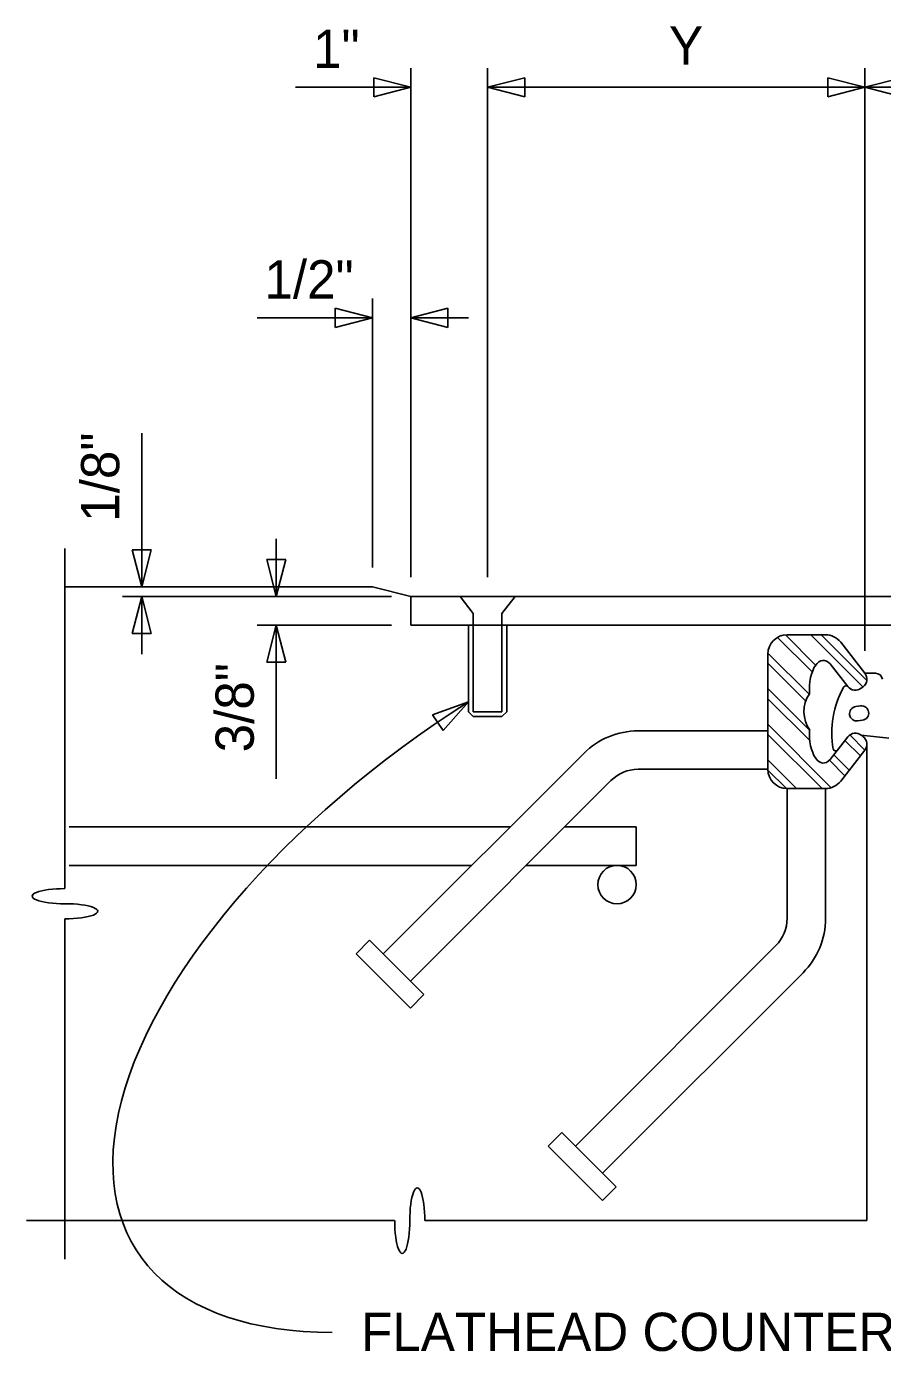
# Model space of a CAD drawing. Extents: x 19590 to 20151, y 19944 to 20103.
# Drawn here: x 19681.44 to 19692.57, y 20061.56 to 20078.8 of the extents above; entities that cross this region are included whole.
import ezdxf

# ---------------------------------------------------------------- set-up
doc = ezdxf.new("R2010")
doc.units = 0
for name, color, linetype in [('DETAIL_PR', 7, 'Continuous'), ('DETAIL_TEXT_DIMEN_PR', 7, 'Continuous'), ('Level 1', 7, 'Continuous')]:
    doc.layers.add(name, color=color, linetype=linetype)

# ---------------------------------------------------------------- blocks, each defined once
blk = doc.blocks.new('BRE')
at = {"layer": 'DETAIL_PR'}
for centre, ratio, start_param, end_param in [((0, 0.098), 0.230206, 4.712389, 7.853982), ((0, -0.098), 0.230204, 1.570796, 4.712389)]:
    blk.add_ellipse(centre, major_axis=(-0.427, 0), ratio=ratio, start_param=start_param, end_param=end_param, dxfattribs=at)

msp = doc.modelspace()

# ---------------------------------------------------------------- linework, layer by layer
at = {"layer": 'DETAIL_PR'}
for p, q in [((19685.936, 20071.509), (19681.936, 20071.509)), ((19685.936, 20071.509), (19681.936, 20071.509)), ((19686.436, 20071.384), (19685.936, 20071.509)), ((19686.436, 20071.384), (19685.936, 20071.509)), ((19698.811, 20071.384), (19686.436, 20071.384)), ((19686.436, 20071.384), (19686.436, 20071.009)), ((19698.811, 20071.384), (19686.436, 20071.384)), ((19686.436, 20071.384), (19686.436, 20071.009)), ((19687.248, 20071.161), (19687.077, 20071.384)), ((19687.077, 20071.384), (19687.794, 20071.384)), ((19687.248, 20071.161), (19687.077, 20071.384)), ((19687.077, 20071.384), (19687.794, 20071.384)), ((19687.794, 20071.384), (19687.623, 20071.161)), ((19687.794, 20071.384), (19687.623, 20071.161)), ((19687.248, 20069.884), (19687.248, 20071.161)), ((19687.248, 20069.884), (19687.248, 20071.161)), ((19687.623, 20071.161), (19687.623, 20069.884)), ((19687.623, 20071.161), (19687.623, 20069.884)), ((19686.436, 20071.009), (19698.936, 20071.009)), ((19686.436, 20071.009), (19698.936, 20071.009)), ((19687.186, 20069.884), (19687.186, 20071.009)), ((19687.186, 20069.884), (19687.186, 20071.009)), ((19687.686, 20071.009), (19687.686, 20069.884)), ((19687.686, 20071.009), (19687.686, 20069.884)), ((19691.21, 20070.851), (19691.659, 20070.401)), ((19691.21, 20070.851), (19691.659, 20070.401)), ((19691.31, 20070.884), (19691.704, 20070.49)), ((19691.31, 20070.884), (19691.704, 20070.49)), ((19691.333, 20070.884), (19691.833, 20070.884)), ((19691.333, 20070.884), (19691.833, 20070.884)), ((19691.641, 20070.884), (19692.319, 20070.206)), ((19691.641, 20070.884), (19692.319, 20070.206)), ((19691.774, 20070.884), (19692.369, 20070.288)), ((19691.774, 20070.884), (19692.369, 20070.288)), ((19691.083, 20070.646), (19691.619, 20070.111)), ((19691.083, 20070.646), (19691.619, 20070.111)), ((19691.083, 20069.134), (19691.083, 20070.634)), ((19691.083, 20069.134), (19691.083, 20070.634)), ((19692.031, 20070.787), (19692.344, 20070.384)), ((19692.031, 20070.787), (19692.344, 20070.384)), ((19691.083, 20070.513), (19691.575, 20070.021)), ((19691.083, 20070.513), (19691.575, 20070.021)), ((19692.122, 20070.211), (19691.892, 20070.508)), ((19692.122, 20070.211), (19691.892, 20070.508)), ((19692.482, 20070.384), (19692.344, 20070.384)), ((19692.482, 20070.384), (19692.344, 20070.384)), ((19691.083, 20070.184), (19691.622, 20069.646)), ((19691.083, 20070.184), (19691.622, 20069.646)), ((19692.322, 20070.208), (19692.298, 20070.189)), ((19692.322, 20070.208), (19692.298, 20070.189)), ((19692.322, 20070.208), (19692.298, 20070.189)), ((19692.322, 20070.208), (19692.298, 20070.189)), ((19691.083, 20070.052), (19691.628, 20069.507)), ((19691.083, 20070.052), (19691.628, 20069.507)), ((19692.227, 20069.95), (19692.289, 20069.958)), ((19692.227, 20069.95), (19692.289, 20069.958)), ((19687.186, 20069.884), (19687.248, 20069.821)), ((19687.186, 20069.884), (19687.248, 20069.821)), ((19687.623, 20069.884), (19687.248, 20069.884)), ((19687.623, 20069.884), (19687.248, 20069.884)), ((19687.623, 20069.821), (19687.248, 20069.821)), ((19687.623, 20069.821), (19687.248, 20069.821)), ((19687.686, 20069.884), (19687.623, 20069.821)), ((19687.686, 20069.884), (19687.623, 20069.821)), ((19692.314, 20069.772), (19692.252, 20069.764)), ((19692.314, 20069.772), (19692.252, 20069.764)), ((19691.083, 20069.634), (19689.394, 20069.634)), ((19691.083, 20069.634), (19689.394, 20069.634)), ((19691.083, 20069.72), (19691.908, 20068.895)), ((19691.083, 20069.72), (19691.908, 20068.895)), ((19691.083, 20069.588), (19691.787, 20068.884)), ((19691.083, 20069.588), (19691.787, 20068.884)), ((19691.892, 20069.26), (19692.122, 20069.556)), ((19691.892, 20069.26), (19692.122, 20069.556)), ((19691.989, 20069.385), (19692.122, 20069.556)), ((19691.989, 20069.385), (19692.122, 20069.556)), ((19692.086, 20069.51), (19692.287, 20069.31)), ((19692.086, 20069.51), (19692.287, 20069.31)), ((19692.148, 20069.581), (19692.345, 20069.384)), ((19692.148, 20069.581), (19692.345, 20069.384)), ((19692.298, 20069.578), (19692.322, 20069.559)), ((19692.298, 20069.578), (19692.658, 20069.541)), ((19692.298, 20069.578), (19692.322, 20069.559)), ((19692.298, 20069.578), (19692.658, 20069.541)), ((19692.37, 20069.454), (19692.37, 20063.262)), ((19692.37, 20069.454), (19692.37, 20063.262)), ((19688.687, 20069.341), (19686.078, 20066.732)), ((19688.687, 20069.341), (19686.078, 20066.732)), ((19691.083, 20069.256), (19691.456, 20068.884)), ((19691.083, 20069.256), (19691.456, 20068.884)), ((19691.942, 20069.324), (19692.142, 20069.123)), ((19691.942, 20069.324), (19692.142, 20069.123)), ((19692.344, 20069.384), (19692.031, 20068.98)), ((19692.344, 20069.384), (19692.031, 20068.98)), ((19691.083, 20069.134), (19689.394, 20069.134)), ((19691.083, 20069.134), (19689.394, 20069.134)), ((19691.083, 20069.124), (19691.323, 20068.884)), ((19691.083, 20069.124), (19691.323, 20068.884)), ((19691.885, 20069.251), (19692.085, 20069.05)), ((19691.885, 20069.251), (19692.085, 20069.05)), ((19689.04, 20068.987), (19686.432, 20066.378)), ((19689.04, 20068.987), (19686.432, 20066.378)), ((19691.333, 20068.884), (19691.333, 20067.194)), ((19691.833, 20068.884), (19691.333, 20068.884)), ((19691.333, 20068.884), (19691.333, 20067.194)), ((19691.833, 20068.884), (19691.333, 20068.884)), ((19691.833, 20068.884), (19691.833, 20067.194)), ((19691.833, 20068.884), (19691.833, 20067.194)), ((19681.991, 20068.384), (19687.73, 20068.384)), ((19681.991, 20068.384), (19687.73, 20068.384)), ((19688.437, 20068.384), (19689.37, 20068.384)), ((19688.437, 20068.384), (19689.37, 20068.384)), ((19689.37, 20068.384), (19689.37, 20067.884)), ((19689.37, 20068.384), (19689.37, 20067.884)), ((19681.991, 20067.884), (19687.23, 20067.884)), ((19681.991, 20067.884), (19687.23, 20067.884)), ((19687.937, 20067.884), (19689.37, 20067.884)), ((19687.937, 20067.884), (19689.37, 20067.884)), ((19685.901, 20066.909), (19685.725, 20066.732)), ((19685.901, 20066.909), (19685.725, 20066.732)), ((19685.901, 20066.909), (19686.608, 20066.202)), ((19685.901, 20066.909), (19686.608, 20066.202)), ((19691.187, 20066.841), (19688.578, 20064.232)), ((19691.187, 20066.841), (19688.578, 20064.232)), ((19685.725, 20066.732), (19686.432, 20066.025)), ((19685.725, 20066.732), (19686.432, 20066.025)), ((19691.54, 20066.487), (19688.932, 20063.878)), ((19691.54, 20066.487), (19688.932, 20063.878)), ((19686.608, 20066.202), (19686.432, 20066.025)), ((19686.608, 20066.202), (19686.432, 20066.025)), ((19688.401, 20064.409), (19688.225, 20064.232)), ((19688.401, 20064.409), (19688.225, 20064.232)), ((19688.401, 20064.409), (19689.108, 20063.702)), ((19688.401, 20064.409), (19689.108, 20063.702)), ((19688.225, 20064.232), (19688.932, 20063.525)), ((19688.225, 20064.232), (19688.932, 20063.525)), ((19689.108, 20063.702), (19688.932, 20063.525)), ((19689.108, 20063.702), (19688.932, 20063.525))]:
    msp.add_line(p, q, dxfattribs=at)
msp.add_circle((19689.12, 20067.634), 0.25, dxfattribs=at)
msp.add_circle((19689.12, 20067.634), 0.25, dxfattribs=at)
for centre, radius, start, end in [((19691.333, 20070.634), 0.25, 90, 180), ((19691.333, 20070.634), 0.25, 90, 180), ((19691.833, 20070.634), 0.25, 37.857, 90), ((19691.833, 20070.634), 0.25, 37.857, 90), ((19692.246, 20070.307), 0.125, 307.857, 37.857), ((19692.246, 20070.307), 0.125, 307.857, 37.857), ((19692.246, 20070.307), 0.125, 307.857, 37.857), ((19692.246, 20070.307), 0.125, 307.857, 37.857), ((19692.482, 20070.29), 0.0938, 9.7762, 90), ((19692.482, 20070.29), 0.0938, 9.7762, 90), ((19691.971, 20069.884), 0.419, 146.3205, 214.9742), ((19691.971, 20069.884), 0.419, 146.3205, 214.9742), ((19693.139, 20069.607), 1.224, 150.7366, 189.8297), ((19693.139, 20069.607), 1.224, 150.7366, 189.8297), ((19692.099, 20070.19), 0.0312, 38.6221, 150.7366), ((19692.099, 20070.19), 0.0312, 38.6221, 150.7366), ((19692.221, 20070.288), 0.125, 217.857, 307.857), ((19692.221, 20070.288), 0.125, 217.857, 307.857), ((19692.221, 20070.288), 0.125, 218.6221, 307.857), ((19692.221, 20070.288), 0.125, 218.6221, 307.857), ((19692.239, 20069.857), 0.0938, 97.5995, 189.7762), ((19692.239, 20069.857), 0.0938, 97.5995, 189.7762), ((19692.301, 20069.865), 0.0938, 9.7762, 97.5995), ((19692.301, 20069.865), 0.0938, 9.7762, 97.5995), ((19692.239, 20069.857), 0.0938, 189.7762, 277.5995), ((19692.239, 20069.857), 0.0938, 189.7762, 277.5995), ((19692.301, 20069.865), 0.0937, 277.5995, 9.7762), ((19692.301, 20069.865), 0.0937, 277.5995, 9.7762), ((19689.394, 20068.634), 1, 90, 135), ((19689.394, 20068.634), 1, 90, 135), ((19692.221, 20069.48), 0.125, 52.143, 142.143), ((19692.221, 20069.48), 0.125, 52.143, 142.143), ((19692.221, 20069.48), 0.125, 52.143, 142.143), ((19692.221, 20069.48), 0.125, 52.143, 142.143), ((19692.246, 20069.46), 0.125, 322.143, 52.143), ((19692.246, 20069.46), 0.125, 322.143, 52.143), ((19691.964, 20069.404), 0.0312, 189.8297, 322.143), ((19691.964, 20069.404), 0.0312, 189.8297, 322.143), ((19689.394, 20068.634), 0.5, 90, 135), ((19689.394, 20068.634), 0.5, 90, 135), ((19691.333, 20069.134), 0.25, 180, 270), ((19691.333, 20069.134), 0.25, 180, 270), ((19691.833, 20069.134), 0.25, 270, 322.143), ((19691.833, 20069.134), 0.25, 270, 322.143), ((19690.833, 20067.194), 0.5, 315, 360), ((19690.833, 20067.194), 0.5, 315, 360), ((19690.833, 20067.194), 1, 315, 0), ((19690.833, 20067.194), 1, 315, 0)]:
    msp.add_arc(centre, radius, start, end, dxfattribs=at)
for centre, major_axis, start_param, end_param in [((19691.817, 20070.127), (-0.016, 0.425), 5.802216, 7.862347), ((19691.817, 20070.127), (-0.016, 0.425), 5.802216, 7.862347), ((19691.817, 20069.64), (0.016, 0.425), 1.562431, 3.622562), ((19691.817, 20069.64), (0.016, 0.425), 1.562431, 3.622562)]:
    msp.add_ellipse(centre, major_axis=major_axis, ratio=0.457019, start_param=start_param, end_param=end_param, dxfattribs=at)
at = {"layer": 'DETAIL_TEXT_DIMEN_PR'}
for p, q in [((19686.436, 20071.634), (19686.436, 20078.259)), ((19686.436, 20071.634), (19686.436, 20078.259)), ((19687.436, 20071.634), (19687.436, 20078.259)), ((19687.436, 20071.634), (19687.436, 20078.259)), ((19692.344, 20070.676), (19692.344, 20078.259)), ((19692.344, 20070.676), (19692.344, 20078.259)), ((19685.954, 20078.133), (19686.436, 20078.009)), ((19685.954, 20077.884), (19685.954, 20078.133)), ((19685.954, 20078.133), (19686.436, 20078.009)), ((19685.954, 20077.884), (19685.954, 20078.133)), ((19687.918, 20078.133), (19687.436, 20078.009)), ((19687.918, 20078.133), (19687.436, 20078.009)), ((19687.918, 20077.884), (19687.918, 20078.133)), ((19687.918, 20077.884), (19687.918, 20078.133)), ((19691.862, 20078.133), (19692.344, 20078.009)), ((19691.862, 20077.884), (19691.862, 20078.133)), ((19691.862, 20078.133), (19692.344, 20078.009)), ((19691.862, 20077.884), (19691.862, 20078.133)), ((19692.826, 20078.133), (19692.344, 20078.009)), ((19692.826, 20078.133), (19692.344, 20078.009)), ((19686.436, 20078.009), (19685.954, 20077.884)), ((19686.436, 20078.009), (19685.954, 20077.884)), ((19692.344, 20078.009), (19687.436, 20078.009)), ((19687.436, 20078.009), (19687.918, 20077.884)), ((19692.344, 20078.009), (19687.436, 20078.009)), ((19687.436, 20078.009), (19687.918, 20077.884)), ((19692.344, 20078.009), (19691.862, 20077.884)), ((19692.344, 20078.009), (19691.862, 20077.884)), ((19692.344, 20078.009), (19694.515, 20078.009)), ((19692.344, 20078.009), (19692.826, 20077.884)), ((19692.344, 20078.009), (19694.515, 20078.009)), ((19692.344, 20078.009), (19692.826, 20077.884)), ((19685.454, 20075.133), (19685.936, 20075.009)), ((19685.454, 20074.884), (19685.454, 20075.133)), ((19685.454, 20075.133), (19685.936, 20075.009)), ((19685.454, 20074.884), (19685.454, 20075.133)), ((19685.936, 20071.759), (19685.936, 20075.259)), ((19685.936, 20071.759), (19685.936, 20075.259)), ((19686.918, 20075.133), (19686.436, 20075.009)), ((19686.918, 20075.133), (19686.436, 20075.009)), ((19686.918, 20074.884), (19686.918, 20075.133)), ((19686.918, 20074.884), (19686.918, 20075.133)), ((19685.936, 20075.009), (19685.454, 20074.884)), ((19685.936, 20075.009), (19685.454, 20074.884)), ((19686.436, 20075.009), (19686.918, 20074.884)), ((19686.436, 20075.009), (19686.918, 20074.884)), ((19681.936, 20067.582), (19681.936, 20072.009)), ((19681.936, 20067.582), (19681.936, 20072.009)), ((19682.811, 20071.991), (19682.936, 20071.509)), ((19683.06, 20071.991), (19682.811, 20071.991)), ((19682.811, 20071.991), (19682.936, 20071.509)), ((19683.06, 20071.991), (19682.811, 20071.991)), ((19682.936, 20071.509), (19683.06, 20071.991)), ((19682.936, 20071.509), (19683.06, 20071.991)), ((19684.561, 20071.866), (19684.686, 20071.384)), ((19684.81, 20071.866), (19684.561, 20071.866)), ((19684.561, 20071.866), (19684.686, 20071.384)), ((19684.81, 20071.866), (19684.561, 20071.866)), ((19684.686, 20071.384), (19684.81, 20071.866)), ((19684.686, 20071.384), (19684.81, 20071.866)), ((19686.186, 20071.384), (19682.686, 20071.384)), ((19686.186, 20071.384), (19682.686, 20071.384)), ((19682.936, 20071.384), (19682.811, 20070.902)), ((19682.936, 20071.384), (19682.811, 20070.902)), ((19683.06, 20070.902), (19682.936, 20071.384)), ((19683.06, 20070.902), (19682.936, 20071.384)), ((19686.186, 20071.009), (19684.436, 20071.009)), ((19686.186, 20071.009), (19684.436, 20071.009)), ((19684.686, 20071.009), (19684.561, 20070.527)), ((19684.686, 20071.009), (19684.561, 20070.527)), ((19684.81, 20070.527), (19684.686, 20071.009)), ((19684.81, 20070.527), (19684.686, 20071.009)), ((19682.811, 20070.902), (19683.06, 20070.902)), ((19682.811, 20070.902), (19683.06, 20070.902)), ((19684.561, 20070.527), (19684.81, 20070.527)), ((19684.561, 20070.527), (19684.81, 20070.527)), ((19687.186, 20070.01), (19686.717, 20069.843)), ((19687.186, 20070.01), (19686.717, 20069.843)), ((19686.857, 20069.637), (19687.186, 20070.01)), ((19686.857, 20069.637), (19687.186, 20070.01)), ((19686.717, 20069.843), (19686.857, 20069.637)), ((19686.717, 20069.843), (19686.857, 20069.637)), ((19681.936, 20062.762), (19681.936, 20067.189)), ((19681.936, 20062.762), (19681.936, 20067.189)), ((19681.436, 20063.262), (19686.226, 20063.262)), ((19681.436, 20063.262), (19686.226, 20063.262)), ((19692.37, 20063.262), (19686.62, 20063.262)), ((19692.37, 20063.262), (19686.62, 20063.262))]:
    msp.add_line(p, q, dxfattribs=at)
msp.add_ellipse((19689.17, 20066.887), major_axis=(6.306, 4.007), ratio=0.495228, start_param=1.570796, end_param=3.803242, dxfattribs=at)
msp.add_ellipse((19689.17, 20066.887), major_axis=(6.306, 4.007), ratio=0.495228, start_param=1.570796, end_param=3.803242, dxfattribs=at)
at = {"layer": 'Level 1'}
for p, q in [((19684.936, 20078.009), (19686.436, 20078.009)), ((19684.936, 20078.009), (19686.436, 20078.009)), ((19684.436, 20075.009), (19685.936, 20075.009)), ((19684.436, 20075.009), (19685.936, 20075.009)), ((19687.186, 20075.009), (19686.436, 20075.009)), ((19687.186, 20075.009), (19686.436, 20075.009)), ((19682.936, 20071.509), (19682.936, 20073.509)), ((19682.936, 20071.509), (19682.936, 20073.509)), ((19684.686, 20072.134), (19684.686, 20071.384)), ((19684.686, 20072.134), (19684.686, 20071.384)), ((19682.936, 20070.634), (19682.936, 20071.384)), ((19682.936, 20070.634), (19682.936, 20071.384)), ((19684.686, 20071.009), (19684.686, 20069.009)), ((19684.686, 20071.009), (19684.686, 20069.009))]:
    msp.add_line(p, q, dxfattribs=at)

# ---------------------------------------------------------------- block references
for p, rotation in [((19681.936, 20067.385), 180), ((19681.936, 20067.385), 180), ((19686.423, 20063.262), 90), ((19686.423, 20063.262), 90)]:
    msp.add_blockref('BRE', p, dxfattribs=dict(at, rotation=rotation))

# ---------------------------------------------------------------- texts
at = {"layer": 'DETAIL_TEXT_DIMEN_PR'}
for s, height, p in [('1"', 0.4976, (19685.165, 20078.26)), ('1"', 0.4976, (19685.165, 20078.26)), ('Y', 0.498, (19689.796, 20078.302)), ('Y', 0.498, (19689.796, 20078.302)), ('1/2"', 0.4976, (19684.532, 20075.26)), ('1/2"', 0.4976, (19684.532, 20075.26)), ('FLATHEAD COUNTERSUNK', 0.49762, (19685.79, 20061.566)), ('FLATHEAD COUNTERSUNK', 0.49762, (19685.79, 20061.566))]:
    msp.add_text(s, height=height, dxfattribs=at).set_placement(p)
for s, p in [('1/8"', (19682.643, 20072.355)), ('1/8"', (19682.643, 20072.355)), ('3/8"', (19684.393, 20069.355)), ('3/8"', (19684.393, 20069.355))]:
    msp.add_text(s, height=0.4976, rotation=90, dxfattribs=at).set_placement(p)

doc.saveas('drawing.dxf')
